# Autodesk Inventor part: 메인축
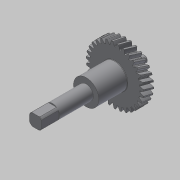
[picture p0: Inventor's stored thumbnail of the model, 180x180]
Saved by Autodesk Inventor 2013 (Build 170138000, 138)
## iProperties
Created: 2017-11
Part Number: 메인축
Material: 강철, 탄소
Document SubType Name: Modeling
Designer: mduedu
Categories: <?xml version="1.0" encoding="UTF-16"?> <MemberInstance><Categories><FamilyTemplate><FamilyTemplateParameter ValueType="xs:double" Id="1" ObjectReferenceKey="da
Density: 7.85 g/cm^3
Mass: 605.821 g
Surface Area: 183.17 cm^2
Volume: 77.1747 cm^3
CustomPartVersion: 1
Author: mduedu
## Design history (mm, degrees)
sketch "Sketch1"
  geometry: C1 r 34.094 at (0, 0)
  constraints: 1 centre point
  dimensions: "d0" = 68.18712 diameter of C1 (= da_da)
extrude "Extrusion1" new body sketch "Sketch1" distance "d1" = 12 (= da_b); taper "d2" = 0 deg
workplane "Work Plane2"
sketch "Sketch2"
  geometry: C1 r 34.094 at (0, 0) reference; C2 r 32.094 at (0, 0)
  constraints: 1 centre point, 1 coincident
  dimensions: "d3" = 64.18712 diameter of C2 (= da_dw)
feature "피치 지름" sketch "Sketch2" dims "d4" = 10, "d5" = 0
workplane "Work Plane8"
workplane "Work Plane9"
feature "스퍼 기어" dims "da_b" = 12, "da_d" = 64.18712, "da_aw" = 54.86964, "da_da" = 68.18712, "da_df" = 59.18712, "da_dw" = 64.18712, angle "da_beta" = 15 deg, "da_lefttooth" = 0, "da_righttooth" = 10
sketch "스케치3"
  geometry: C1 r 15 at (0, 0); 1 further point
  constraints: 1 centre point, 1 coincident
  dimensions: "d49" = 30 diameter of C1
extrude "돌출2" join sketch "스케치3" distance "d50" = 34; taper "d51" = 0 deg
sketch "스케치4"
  geometry: C1 r 8.5 at (0, 0); 1 further point
  constraints: 1 centre point, 1 coincident
  dimensions: "d52" = 17 diameter of C1
extrude "돌출3" join sketch "스케치4" distance "d53" = 60; taper "d54" = 0 deg
sketch "스케치5"
  geometry: C1 r 7.5 at (0, 0); 1 further point
  constraints: 1 centre point, 1 coincident
  dimensions: "d55" = 15 diameter of C1
extrude "돌출4" join sketch "스케치5" distance "d56" = 16; taper "d57" = 0 deg
sketch "스케치6"
  geometry: C1 r 4 at (0, 0); 1 further point
  constraints: 1 centre point, 1 coincident
  dimensions: "d58" = 8 diameter of C1
extrude "돌출5" join sketch "스케치6" distance "d59" = 7; taper "d60" = 0 deg
chamfer "모따기1" distance "d61" = 0.5; stored, may be unused: second distance "d62" = 2, angle "d63" = 45 deg
fillet "모깎기1" dims "d64" = 0.5
sketch "스케치7"
  geometry: L1 (-7, -7)-(7, -7); L2 (7, -7)-(7, 7); L3 (7, 7)-(-7, 7); L4 (-7, 7)-(-7, -7); L5 (-7, -7)-(7, 7); L6 (7, -7)-(-7, 7); L7 (-10, -10)-(10, -10); L8 (10, -10)-(10, 10); L9 (10, 10)-(-10, 10); L10 (-10, 10)-(-10, -10); L11 (-10, -10)-(10, 10); L12 (10, -10)-(-10, 10); 1 further point
  constraints: 24 end point, 4 midpoint, 4 parallel, 2 horizontal, 2 perpendicular
  dimensions: "d65" = 14 distance of L3.end L2.end; "d66" = 14 distance of L2.end L1.end; "d67" = 20 distance of L9.end L8.end; "d68" = 20 distance of L8.end L7.end
extrude "돌출6" cut sketch "스케치7" distance "d69" = 20; taper "d70" = 0 deg
body "Solid1"
body "Srf1"
other parameters: "d16" = 54.86964 (= da_aw), "d17" = 0, "d34" = 1.01342 (computed from da_z), "d39" = 0, "d41" = 0, "d43" = 54.86964 (= da_aw), "d46" = 54.86964 (= da_aw), "d47" = 0, "d48" = 0
